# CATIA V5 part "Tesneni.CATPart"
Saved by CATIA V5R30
Part number: Tesneni
Bounding box of the stored display mesh (mm): x 0 to 1.2, y -6 to 6, z -6 to 6
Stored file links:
  E:\Bakalarka\Model\Forma_v7\Tesneni.CATPart
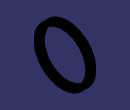
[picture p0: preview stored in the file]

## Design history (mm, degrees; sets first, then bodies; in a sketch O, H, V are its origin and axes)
Body1 (main body)
  Sketch1 on yz-plane, origin (0, 0, 0), H (0, 1, 0), V (0, 0, 1)
    circle A1 centre (0, 0) radius 6
    circle A2 centre (0, 0) radius 5
    radius A2 = 5
    radius A1 = 6
  Pad1: profile Sketch1, direction (1, 0, 0), length 1.2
